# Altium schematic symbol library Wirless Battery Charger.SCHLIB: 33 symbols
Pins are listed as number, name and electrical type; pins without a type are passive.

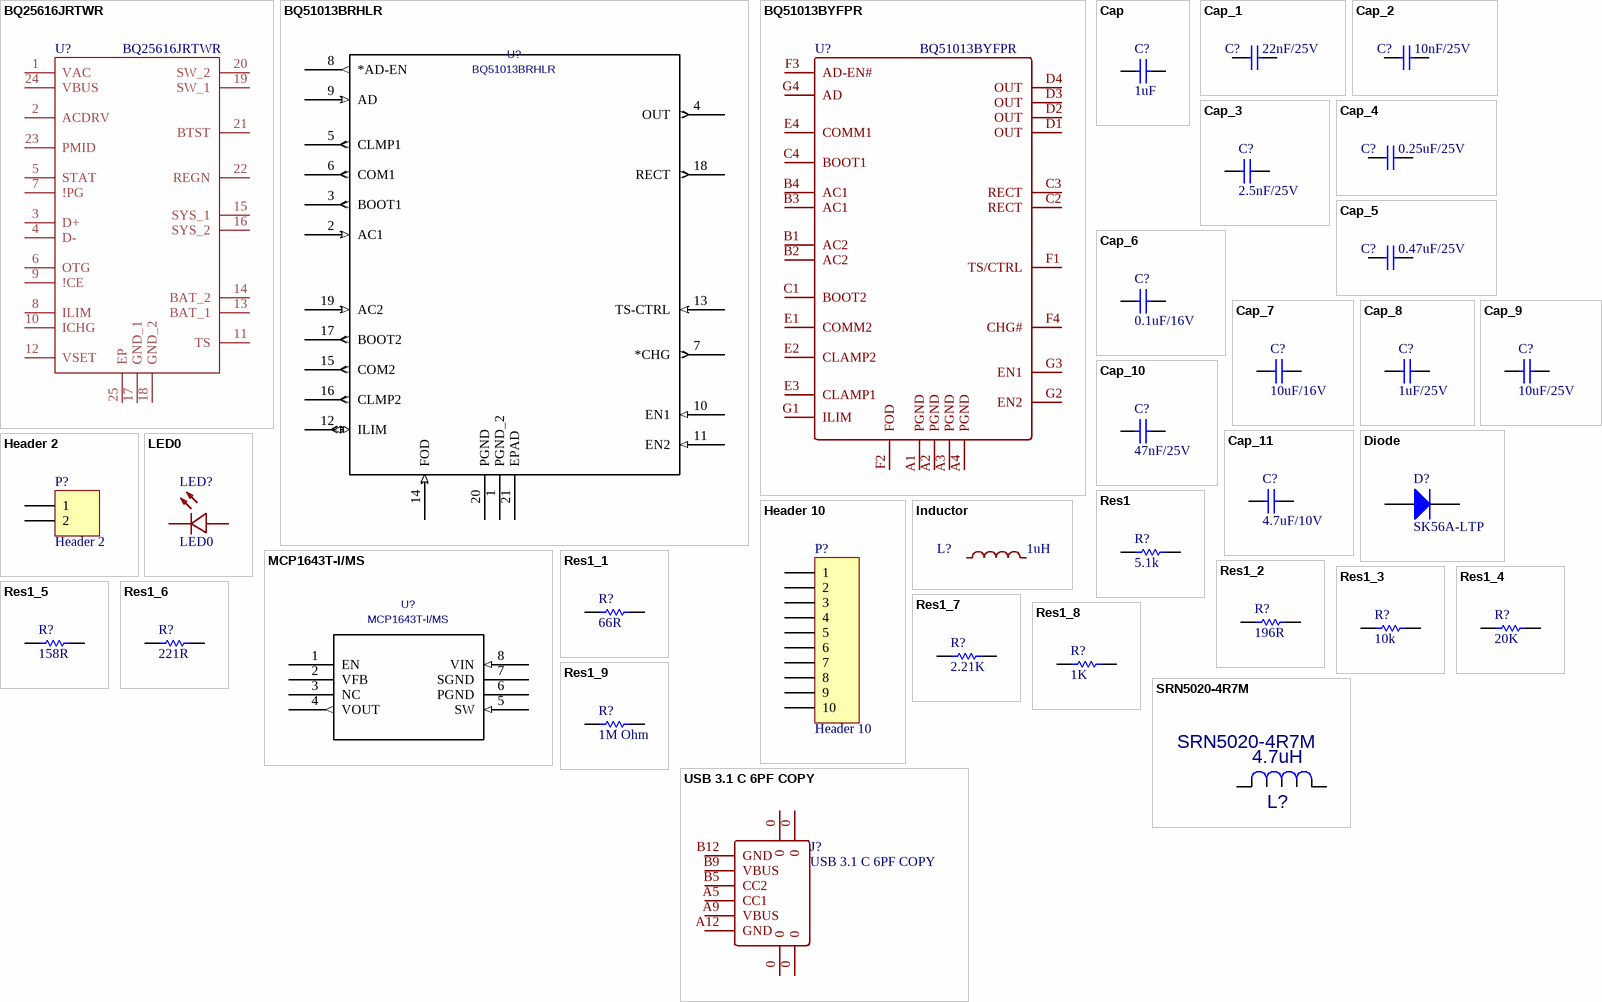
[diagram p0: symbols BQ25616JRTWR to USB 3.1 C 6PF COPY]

## BQ25616JRTWR
designator U?
footprint QFN50P400X400X80
pins: 1 VAC, 2 ACDRV, 3 D+, 4 D-, 5 STAT, 6 OTG, 7 !PG, 8 ILIM, 9 !CE, 10 ICHG, 11 TS, 12 VSET, 13 BAT_1, 14 BAT_2, 15 SYS_1, 16 SYS_2, 17 GND_1, 18 GND_2, 19 SW_1, 20 SW_2, 21 BTST, 22 REGN, 23 PMID, 24 VBUS, 25 EP

## BQ51013BRHLR
designator U?
Mfr_Name: Texas Instruments
footprint RHL20_2P05X3P05
pins: 1 PGND_2 (power), 2 AC1 (in), 3 BOOT1 (out), 4 OUT (out), 5 CLMP1 (out), 6 COM1 (out), 7 *CHG (out), 8 *AD-EN (out), 9 AD (in), 10 EN1 (in), 11 EN2 (in), 12 ILIM (io), 13 TS-CTRL (in), 14 FOD (in), 15 COM2 (out), 16 CLMP2 (out), 17 BOOT2 (out), 18 RECT (out), 19 AC2 (in), 20 PGND (power), 21 EPAD

## BQ51013BYFPR
designator U?
footprint DSBGA-28_L3.0-W1.9-R7-C4-P0.40-BL
pins: A1 PGND, A2 PGND, A3 PGND, A4 PGND, B1 AC2, B2 AC2, B3 AC1, B4 AC1, C1 BOOT2, C2 RECT, C3 RECT, C4 BOOT1, D1 OUT, D2 OUT, D3 OUT, D4 OUT, E1 COMM2, E2 CLAMP2, E3 CLAMP1, E4 COMM1, F1 TS/CTRL, F2 FOD, F3 AD-EN#, F4 CHG#, G1 ILIM, G2 EN2, G3 EN1, G4 AD

## Cap
designator C?  value 1uF  (hidden comment: Cap)
Capacitor
simulation model CAP (Capacitor)
signal-integrity model Cap
footprint 0805-CAP
pins: 1, 2

## Cap_1
designator C?, comment value 22nF/25V  (hidden comment: Cap)
Capacitor
simulation model CAP (Capacitor)
signal-integrity model Cap
footprint 0402-A (Chip Inductor, Body 1.0x0.5mm, IPC High Density)
pins: 1, 2

## Cap_2
designator C?, comment value 10nF/25V  (hidden comment: Cap)
Capacitor
simulation model CAP (Capacitor)
signal-integrity model Cap
footprint 0402-A (Chip Inductor, Body 1.0x0.5mm, IPC High Density)
pins: 1, 2

## Cap_3
designator C?, comment value 2.5nF/25V  (hidden comment: Cap)
Capacitor
simulation model CAP (Capacitor)
signal-integrity model Cap
footprint 0402-A (Chip Inductor, Body 1.0x0.5mm, IPC High Density)
pins: 1, 2

## Cap_4
designator C?, comment value 0.25uF/25V  (hidden comment: Cap)
Capacitor
simulation model CAP (Capacitor)
signal-integrity model Cap
footprint 0402-A (Chip Inductor, Body 1.0x0.5mm, IPC High Density)
pins: 1, 2

## Cap_5
designator C?, comment value 0.47uF/25V  (hidden comment: Cap)
Capacitor
simulation model CAP (Capacitor)
signal-integrity model Cap
footprint 0402-A (Chip Inductor, Body 1.0x0.5mm, IPC High Density)
pins: 1, 2

## Cap_6
designator C?, comment value 0.1uF/16V  (hidden comment: Cap)
Capacitor
simulation model CAP (Capacitor)
signal-integrity model Cap
footprint 0805-CAP
pins: 1, 2

## Cap_7
designator C?, comment value 10uF/16V  (hidden comment: Cap)
Capacitor
simulation model CAP (Capacitor)
signal-integrity model Cap
footprint 0805-CAP
pins: 1, 2

## Cap_8
designator C?, comment value 1uF/25V  (hidden comment: Cap)
Capacitor
simulation model CAP (Capacitor)
signal-integrity model Cap
footprint 0805-CAP
pins: 1, 2

## Cap_9
designator C?, comment value 10uF/25V  (hidden comment: Cap)
Capacitor
simulation model CAP (Capacitor)
signal-integrity model Cap
footprint 0805-CAP
pins: 1, 2

## Cap_10
designator C?, comment value 47nF/25V  (hidden comment: Cap)
Capacitor
simulation model CAP (Capacitor)
signal-integrity model Cap
footprint 0805-CAP
pins: 1, 2

## Cap_11
designator C?, comment value 4.7uF/10V  (hidden comment: Cap)
Capacitor
simulation model CAP (Capacitor)
signal-integrity model Cap
footprint 0805-CAP
pins: 1, 2

## Diode
designator D?, comment SK56A-LTP
DIODE SCHOTTKY 5A 60V SMA
footprint SMC (DO-214-AB/SMC; 2 C-Bend Leads; Body 7.9 x 5.9 mm, inc. leads (LxW))
simulation model DIODE (Diode)
signal-integrity model Diode
pins: 1 A, 2 K

## Header 2
designator P?
Header, 2-Pin
footprint HDR1X2 (Connector; Header; 2 Position)
signal-integrity model Connector
pins: 1, 2

## Header 10
designator P?
Header, 10-Pin
signal-integrity model Connector
footprint HDR1X10 (Connector; Header; 10 Position)
pins: 1, 2, 3, 4, 5, 6, 7, 8, 9, 10

## Inductor
designator L?, comment 1uH
footprint IND-SMD_L4.1-W3.2
pins: 1, 2

## LED0
designator LED?
footprint 1608[0603]_LED (Chip Capacitor, Body 1.6x0.8mm, IPC High Density)
pins: 1 A, 2 K

## MCP1643T-I/MS
designator U?
Mfr_Name: Microchip; C: Copyright (C) 2018 Accelerated Designs. All rights reserved
footprint MSOP8_MC_MCH
pins: 1 EN, 2 VFB, 3 NC, 4 VOUT (out), 5 SW (in), 6 PGND (power), 7 SGND (power), 8 VIN (in)

## Res1
designator R?  value 5.1k  (hidden comment: Res1)
Resistor
simulation model RESISTOR (Resistor)
signal-integrity model Res
footprint 1608[0603] (Chip Capacitor, Body 1.6x0.8mm, IPC High Density)
pins: 1, 2

## Res1_1
designator R?, comment value 66R  (hidden comment: Res1)
Resistor
simulation model RESISTOR (Resistor)
signal-integrity model Res
footprint 0402-A (Chip Inductor, Body 1.0x0.5mm, IPC High Density)
pins: 1, 2

## Res1_2
designator R?, comment value 196R  (hidden comment: Res1)
Resistor
simulation model RESISTOR (Resistor)
signal-integrity model Res
footprint 0402-A (Chip Inductor, Body 1.0x0.5mm, IPC High Density)
pins: 1, 2

## Res1_3
designator R?, comment value 10k  (hidden comment: Res1)
Resistor
simulation model RESISTOR (Resistor)
signal-integrity model Res
footprint 0402-A (Chip Inductor, Body 1.0x0.5mm, IPC High Density)
pins: 1, 2

## Res1_4
designator R?, comment value 20K  (hidden comment: Res1)
Resistor
simulation model RESISTOR (Resistor)
signal-integrity model Res
footprint 0402-A (Chip Inductor, Body 1.0x0.5mm, IPC High Density)
pins: 1, 2

## Res1_5
designator R?, comment value 158R  (hidden comment: Res1)
Resistor
simulation model RESISTOR (Resistor)
signal-integrity model Res
footprint 0402-A (Chip Inductor, Body 1.0x0.5mm, IPC High Density)
pins: 1, 2

## Res1_6
designator R?, comment value 221R  (hidden comment: Res1)
Resistor
simulation model RESISTOR (Resistor)
signal-integrity model Res
footprint 0402-A (Chip Inductor, Body 1.0x0.5mm, IPC High Density)
pins: 1, 2

## Res1_7
designator R?, comment value 2.21K  (hidden comment: Res1)
Resistor
simulation model RESISTOR (Resistor)
signal-integrity model Res
footprint 0402-A (Chip Inductor, Body 1.0x0.5mm, IPC High Density)
pins: 1, 2

## Res1_8
designator R?, comment value 1K  (hidden comment: Res1)
Resistor
simulation model RESISTOR (Resistor)
signal-integrity model Res
footprint 0402-A (Chip Inductor, Body 1.0x0.5mm, IPC High Density)
pins: 1, 2

## Res1_9
designator R?, comment value 1M Ohm  (hidden comment: Res1)
Resistor
simulation model RESISTOR (Resistor)
signal-integrity model Res
footprint 0402-A (Chip Inductor, Body 1.0x0.5mm, IPC High Density)
pins: 1, 2

## SRN5020-4R7M
designator L?, comment 4.7uH  value SRN5020-4R7M
Mfr_Name: Bourns Electronics; C: Copyright (C) 2015 Accelerated Designs. All rights reserved
footprint IND_BOURNS_SRN50
pins: 1, 2
1 alternate drawing of the same symbol

## USB 3.1 C 6PF COPY
designator J?
footprint USB-C-SMD_TYPE-C-USB-13
pins: 0, 0, 0, 0, A5 CC1, A9 VBUS, A12 GND, B5 CC2, B9 VBUS, B12 GND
